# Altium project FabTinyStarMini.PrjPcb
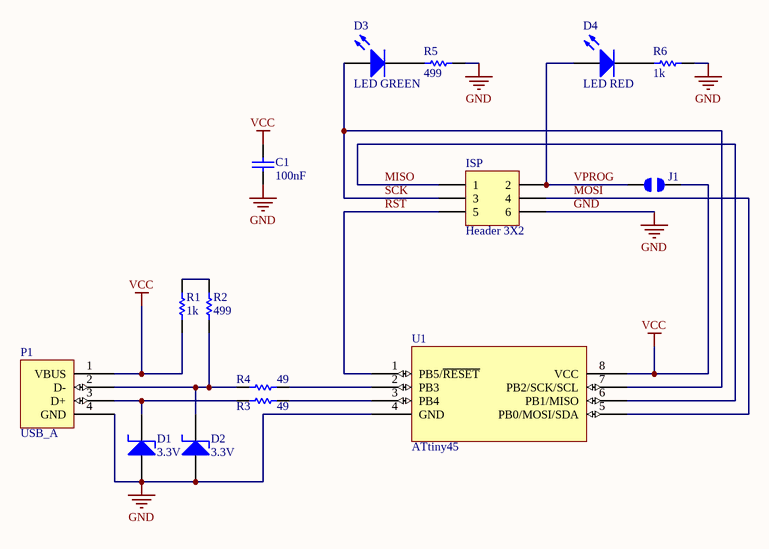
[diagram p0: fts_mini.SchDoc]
1 sheet, 15 parts. Net scope: global (net labels, ports and power ports of the same name join across sheets).
Board file: fts_mini.PcbDoc

## Sheet fts_mini.SchDoc
size A

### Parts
C1  100nF  [1206C]
D1  3.3V  [SOD123]
D2  3.3V  [SOD123]
D3  LED GREEN  [1206LED]
D4  LED RED  [1206LED]
ISP  Header 3X2  [100MIL_SMT_ISP_HEADER]
J1  Solder Jumper  [JMP_1.9mm]  (value not drawn)
P1  USB_A  [USB_PCB]
R1  1k  [1206R]
R2  499  [1206R]
R3  49  [1206R]
R4  49  [1206R]
R5  499  [1206R]
R6  1k  [1206R]
U1  ATtiny45  [SOIC8_WIDE]

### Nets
GND: C1.1 D1.1(A) D2.1(A) ISP.6 P1.4(GND) R5.2 R6.2 U1.4(GND)
VCC: C1.2 J1.2 P1.1(VBUS) R1.1 U1.8(VCC)
MISO: ISP.1 U1.6(PB1/MISO)
MOSI: ISP.4 U1.5(PB0/MOSI/SDA)
RST: ISP.5 U1.1(PB5/~{RESET})
SCK: D3.1(A) ISP.3 U1.7(PB2/SCK/SCL)
VPROG: D4.1(A) ISP.2 J1.1
NetD1_2: D1.2(K) P1.3(D+) R3.2
NetD2_2: D2.2(K) P1.2(D-) R2.1 R4.2
NetD3_2: D3.2(K) R5.1
NetD4_2: D4.2(K) R6.1
NetR1_2: R1.2 R2.2
NetR3_1: R3.1 U1.3(PB4)
NetR4_1: R4.1 U1.2(PB3)

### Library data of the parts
C1 = Capacitor
D1 D2 = Zener Diode
D3 D4 = LED
ISP = Header 3X2: Header, 3-Pin, Dual row
R1-R6 = Resistor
